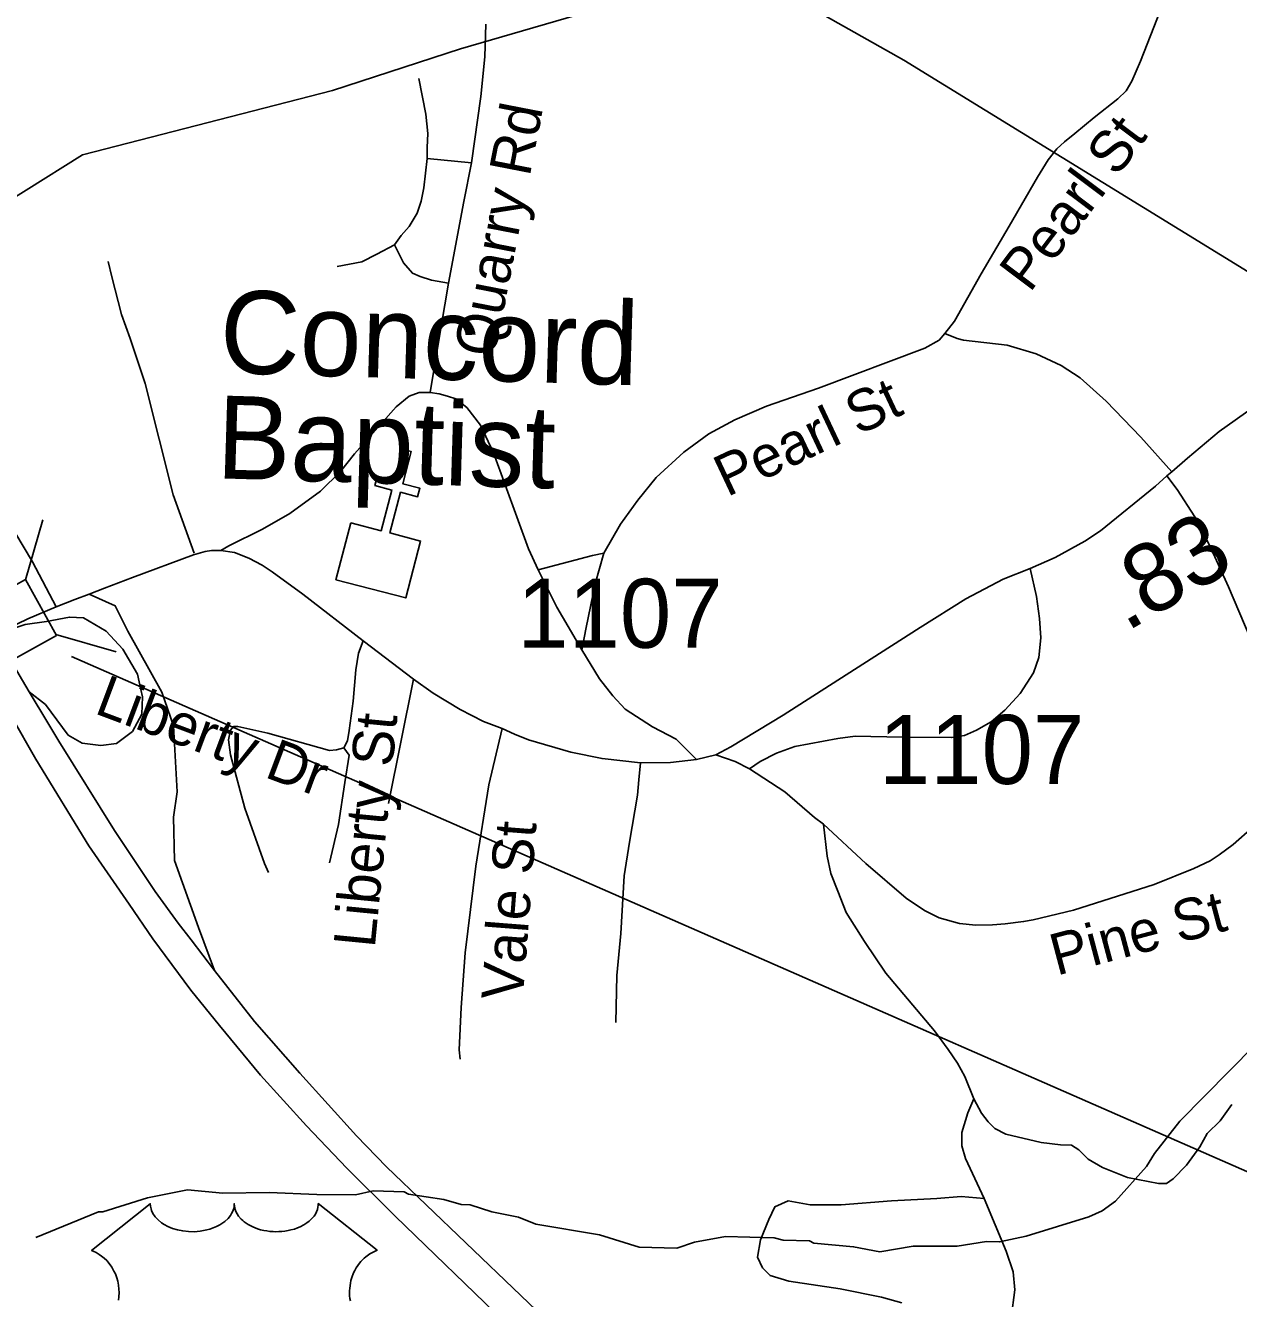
# Model space of a CAD drawing. Extents: x 1159738 to 1321356, y 736314 to 882035.
# Drawn here: x 1281308 to 1283504, y 753698 to 756002 of the extents above; entities that cross this region are included whole.
import ezdxf

# ---------------------------------------------------------------- set-up
doc = ezdxf.new("R2010")
doc.units = 0
for name, color, linetype in [('Exist Cultural Church CELL', 7, 'Continuous'), ('Exist Cultural Church Label', 7, 'Continuous'), ('Exist Hydrographic Misc Water Feature', 7, 'Continuous'), ('Exist Road Non-System Type 51', 7, 'Continuous'), ('Exist Road Non-System Type 51 Label', 7, 'Continuous'), ('Exist Road Primary Interstate Ramp 1 Lane Attributed', 7, 'Continuous'), ('Exist Road Primary US Divided Attributed', 7, 'Continuous'), ('Exist Road Primary US Shield CELL', 7, 'Continuous'), ('Exist Road Secondary Mileage Hundredths English Label', 7, 'Continuous'), ('Exist Road Secondary Structure Standard Bridge CELL', 7, 'Continuous'), ('Exist Road Secondary Structure Standard Bridge Number Label', 7, 'Continuous'), ('Exist Road Secondary Type 51 Attributed', 7, 'Continuous'), ('Exist Road Secondary Type 51 Number Label', 7, 'Continuous'), ('Exist Utilities Electrical Transmission Line', 7, 'Continuous')]:
    doc.layers.add(name, color=color, linetype=linetype)

msp = doc.modelspace()

# ---------------------------------------------------------------- linework, layer by layer
at = {"layer": 'Exist Cultural Church CELL'}
msp.add_lwpolyline([(1281897.2, 755101.7), (1281952.3, 755087.4), (1281971.6, 755161), (1281940.6, 755169.1), (1281944.7, 755184.6), (1281975.6, 755176.5), (1281990.9, 755234.6), (1282006.4, 755230.6), (1281991.1, 755172.4), (1282022.1, 755164.3), (1282018, 755148.8), (1281987.1, 755156.9), (1281967.8, 755083.3), (1282023.5, 755068.6), (1281996.5, 754965.6), (1281870.2, 754998.7)], close=True, dxfattribs=at)
at = {"layer": 'Exist Hydrographic Misc Water Feature'}
msp.add_lwpolyline([(1283532.3, 754155.9), (1283397.4, 754018.6), (1283351.8, 753960), (1283337.1, 753936.4), (1283281.3, 753874), (1283256.8, 753856.7), (1283232.5, 753845.4), (1283119.6, 753810.7), (1283071.3, 753800.1), (1283047.3, 753800.7), (1282994.6, 753792.7), (1282915, 753792.5), (1282854.7, 753782.3), (1282807, 753791.6), (1282735.1, 753797.7), (1282727.3, 753801.9), (1282679.3, 753803.3), (1282663.4, 753807.8), (1282575.5, 753810.3), (1282519.2, 753799.9), (1282486.9, 753788.8), (1282418.9, 753790.7), (1282347.4, 753812.8), (1282232, 753832.1), (1282200.3, 753845), (1282152.5, 753854.4), (1282113, 753867.5), (1282097, 753868), (1282065.2, 753876.9), (1282001.4, 753886.7), (1281993.5, 753890.9), (1281937.5, 753892.5), (1281905.3, 753885.5), (1281835.6, 753885.9), (1281749.5, 753889.9), (1281665.4, 753888.3), (1281601.6, 753894.2), (1281529.2, 753880.2), (1281448.4, 753854.6), (1281440.4, 753854.8), (1281327.1, 753808.1)], dxfattribs=at)
at = {"layer": 'Exist Road Non-System Type 51'}
msp.add_line((1282010.7, 754818.4), (1281965.2, 754593.4), dxfattribs=at)
for points in [[(1282972.4, 755444.5), (1282989.4, 755466.8), (1283038, 755552.4), (1283088.3, 755638.4), (1283140, 755727.2), (1283159.4, 755758.5), (1283175, 755778.5), (1283188.8, 755791), (1283207.6, 755806.4), (1283242.6, 755835.2), (1283285.1, 755869.2), (1283300.1, 755883.6), (1283310.8, 755901.2), (1283326.1, 755936.9), (1283362.4, 756029.5), (1283423.4, 756192.8), (1283428.8, 756213.8), (1283432.2, 756240.4), (1283432.8, 756287.9), (1283427.5, 756356.5), (1283439.4, 756408.9)], [(1280640.2, 755937), (1280709.8, 755992.4), (1280734.1, 755999.3), (1280747.9, 755988.9), (1280770.6, 755949.5), (1280815.5, 755872.8), (1280961.1, 755645.6), (1281020, 755550.2), (1281094.5, 755409.7), (1281321.2, 755031), (1281363.9, 754949.8)], [(1282115.6, 755753.4), (1282132.7, 755873.2), (1282139.6, 755944.8), (1282141.4, 756004.1)], [(1282019.9, 755906), (1282032.8, 755841.4), (1282036.3, 755806), (1282035.4, 755781), (1282035.4, 755761.2)], [(1282035.4, 755761.2), (1282029.4, 755707.7), (1282024.2, 755683.5), (1282017.3, 755662), (1282002.7, 755637.8), (1281988, 755621.4), (1281975.9, 755605)], [(1282035.4, 755761.2), (1282115.6, 755753.4)], [(1282074.1, 755535.6), (1282101.7, 755683.1), (1282115.6, 755753.4)], [(1281975.9, 755605), (1281944.1, 755587.8), (1281917.3, 755574), (1281872.5, 755565.4)], [(1281975.9, 755605), (1281992.3, 755572.3), (1282008.7, 755553.3), (1282022.4, 755547.6), (1282043.1, 755540.7), (1282074.1, 755535.6)], [(1281613.6, 755046.7), (1281575.4, 755152.5), (1281525.2, 755353.6), (1281497.5, 755435.1), (1281481.9, 755478.5), (1281464.6, 755546.9), (1281457.7, 755574.7)], [(1282074.1, 755535.6), (1282054.4, 755421.1), (1282040.6, 755337.5)], [(1282355.1, 755046.6), (1282385.3, 755099.2), (1282416.3, 755142.4), (1282449.9, 755183.8), (1282499.6, 755229.2), (1282545.3, 755262.8), (1282591.9, 755287.8), (1282649.6, 755312.8), (1282743.5, 755345.6), (1282936.2, 755417.8), (1282962, 755432.4), (1282972.4, 755444.5)], [(1282972.4, 755444.5), (1282994.7, 755435.2), (1283005.7, 755432.4), (1283084.9, 755423.4), (1283137.2, 755407.5), (1283182.9, 755386.4), (1283216.9, 755364.3), (1283264, 755321.7), (1283327, 755256.6), (1283383.1, 755194.1)], [(1282040.6, 755337.5), (1282020.8, 755337.5), (1282002.7, 755330.6), (1281979.4, 755311.6), (1281903.6, 755226.2), (1281878.7, 755194.5), (1281842.5, 755159.2), (1281786.5, 755118.6), (1281737.3, 755090.2), (1281676.2, 755060.2), (1281661.6, 755051.7)], [(1282040.6, 755337.5), (1282057.2, 755335.3), (1282071.8, 755331), (1282087.3, 755325.8), (1282107.2, 755310.3), (1282132.1, 755278.4), (1282155.4, 755228.3), (1282218.9, 755054.4), (1282236.2, 755016.4)], [(1283373.8, 755186.8), (1283392.8, 755162), (1283424.6, 755112.4), (1283451.4, 755061.2), (1283485.6, 754986), (1283545.5, 754845.4)], [(1282236.2, 755016.4), (1282334.4, 755042.3), (1282355.1, 755046.6)], [(1282315.4, 754871.5), (1282323.2, 754912.1), (1282339.6, 754991.4), (1282355.1, 755046.6)], [(1282236.2, 755016.4), (1282269.8, 754949.2), (1282315.4, 754871.5)], [(1282618.9, 754656.4), (1282637.8, 754669.7), (1282667.4, 754684.6), (1282700.6, 754697.1), (1282778.5, 754711), (1282809.9, 754715.4), (1282895.4, 754713.9), (1282984.3, 754712.8), (1283007.7, 754716.8), (1283029.6, 754726.3), (1283056, 754741.7), (1283081, 754762.3), (1283108.4, 754792.7), (1283132.6, 754830.3), (1283142.4, 754857.8), (1283145.7, 754893.2), (1283143.5, 754928.7), (1283138, 754968.4), (1283126.7, 755018.8)], [(1281884.6, 754694.3), (1281890.8, 754706.8), (1281894.4, 754725.5), (1281901.5, 754779.1), (1281906, 754835.3), (1281911.3, 754865.7), (1281919.4, 754888)], [(1282315.4, 754871.5), (1282347, 754819.3), (1282371.1, 754788.2), (1282393.5, 754764.1), (1282442.9, 754732.3), (1282485.7, 754710.2), (1282522.6, 754673.2)], [(1281884.6, 754694.3), (1281871.2, 754690.7), (1281858.7, 754689.8), (1281747.2, 754721.1), (1281692.7, 754732.7), (1281684.7, 754732.7), (1281679.4, 754726.4), (1281675.8, 754708.6), (1281679.4, 754681.8), (1281705.2, 754585.3), (1281740.9, 754485.3), (1281748.1, 754468.7)], [(1282170.9, 754729.2), (1282146.8, 754627.4), (1282123.6, 754480.1), (1282103.9, 754323.6), (1282096.8, 754224.5), (1282093.2, 754147.7), (1282095, 754130.8)], [(1281858.7, 754486.2), (1281874.8, 754555.9), (1281886.4, 754631.8), (1281894.4, 754680.9), (1281884.6, 754694.3)], [(1282557.9, 754681.7), (1282592.8, 754669.4), (1282618.9, 754656.4)], [(1282376.6, 754197.5), (1282378.4, 754282.4), (1282385.5, 754358.3), (1282391.8, 754462.7), (1282401.6, 754523.4), (1282415.8, 754608.9), (1282418.5, 754636.5), (1282421.6, 754667.2)], [(1282618.9, 754656.4), (1282682.4, 754614.7), (1282736.3, 754568.6), (1282752.7, 754556.3)], [(1282752.7, 754556.3), (1282758.9, 754498.3), (1282766.1, 754467), (1282778.6, 754434.9), (1282793.7, 754396.5), (1282826.7, 754343.8), (1282865.1, 754286.7), (1282953.3, 754182.5), (1282978.3, 754148.6), (1282995.2, 754123.6), (1283008.6, 754099.5), (1283024.7, 754059.3), (1283038.8, 754033), (1283050.4, 754017.8), (1283062.9, 754005.3), (1283082.5, 753995.5), (1283146.7, 753980.3), (1283181.5, 753975.8), (1283201.2, 753975), (1283214.5, 753966.9), (1283231.5, 753950), (1283257.4, 753934.8), (1283302.9, 753916.9), (1283359.1, 753906.2), (1283373.3, 753906.2), (1283385.6, 753914.2), (1283409.7, 753939.2), (1283433.8, 753972.3), (1283447.1, 753996.4), (1283470.3, 754019.6), (1283491.7, 754049.1)], [(1283529.7, 754551), (1283494.2, 754519.6), (1283468.7, 754500.8), (1283452.6, 754489.6), (1283422.9, 754476), (1283351, 754447.1), (1283205, 754400.5), (1283132.2, 754383.2), (1283114.8, 754379.9), (1283081.4, 754375.8), (1283058.3, 754374.1), (1283028.1, 754373.7), (1282998.5, 754376.2), (1282962.2, 754386.5), (1282935.4, 754400.2), (1282902.3, 754422.1), (1282828.9, 754485.3), (1282752.7, 754556.3)], [(1283024.7, 754059.3), (1283013.8, 754034.1), (1283003.1, 753998.4), (1283003.1, 753974.3), (1283009.3, 753951.1), (1283043.2, 753878.8)], [(1282894.3, 753689.7), (1282857.7, 753700.4), (1282782.7, 753715.5), (1282689.9, 753728.9), (1282656.3, 753739.6), (1282642, 753753), (1282633.1, 753772.6), (1282638.4, 753803.9), (1282653.6, 753840.5), (1282664.3, 753863.7), (1282688.4, 753874.4), (1282728.5, 753867.3), (1282784.7, 753867.3), (1282875.7, 753874.4), (1282957.8, 753878.9), (1283001.5, 753882.5), (1283043.2, 753878.8)], [(1283043.2, 753878.8), (1283083.4, 753783.3), (1283095.9, 753745.8), (1283098.6, 753713.6), (1283092.3, 753662.9)]]:
    msp.add_lwpolyline(points, dxfattribs=at)
at = {"layer": 'Exist Road Primary Interstate Ramp 1 Lane Attributed'}
for points in [[(1281650.6, 754291.4), (1281621.6, 754369.4), (1281577.8, 754490.3), (1281576, 754569.2), (1281583, 754614.8), (1281576, 754734), (1281555, 754795.3), (1281493.6, 754905.7), (1281470.8, 754951.3), (1281423.3, 754972.5)], [(1281253.5, 754899.5), (1281307.6, 754917.6), (1281346.6, 754923.1), (1281387.7, 754930.9), (1281413.2, 754929.8), (1281454.3, 754905.3), (1281484.4, 754873.2), (1281511, 754827.6), (1281517, 754799.9)], [(1281517, 754799.9), (1281520, 754786.5), (1281518.8, 754755.3), (1281502.1, 754724.2), (1281473.3, 754702), (1281444.4, 754698.7), (1281411.1, 754703.1), (1281385.4, 754717.5), (1281344.3, 754773.1), (1281315, 754795.8)]]:
    msp.add_lwpolyline(points, dxfattribs=at)
at = {"layer": 'Exist Road Primary US Divided Attributed'}
for points in [[(1281315, 754795.8), (1281308.9, 754806), (1281253.5, 754899.5)], [(1281205.3, 754875), (1281282.7, 754750.9), (1281327.3, 754673.8), (1281422.8, 754516.8), (1281495.9, 754411.3), (1281539, 754348.9), (1281607.8, 754256.1), (1281659.7, 754192.1), (1281733.9, 754102), (1281817.1, 754010.1), (1281889.7, 753933.7), (1281977.6, 753846.5), (1282175.6, 753654.8), (1282321.8, 753516.3), (1282602, 753249.9), (1282794.5, 753067.1), (1282993.2, 752875.7), (1283115.9, 752762.2), (1283169.4, 752712.1), (1283311, 752579.4), (1283449.2, 752449), (1283551.7, 752350.5), (1283622.4, 752282.2), (1284370.9, 751572.6)], [(1281650.6, 754291.4), (1281608.1, 754346.9), (1281584.4, 754376.9), (1281543.3, 754434.6), (1281469.6, 754544.5), (1281368.7, 754706.3), (1281348.8, 754739.4), (1281315, 754795.8)], [(1284406.3, 751613.3), (1283745.3, 752241.8), (1283636.2, 752347), (1283590.4, 752388.5), (1283450.2, 752521.5), (1283263.2, 752698.3), (1283203.3, 752756.5), (1282971, 752973.8), (1282755.9, 753180.7), (1282403.6, 753512.5), (1282105.3, 753798.8), (1281961.9, 753936.1), (1281907.4, 753991.9), (1281804.9, 754105.5), (1281722.9, 754199.3), (1281650.6, 754291.4)]]:
    msp.add_lwpolyline(points, dxfattribs=at)
at = {"layer": 'Exist Road Primary US Shield CELL'}
msp.add_lwpolyline([(1281476.5, 753694.8), (1281477.3, 753700.9), (1281477.6, 753708.5), (1281477.5, 753714.8), (1281476.6, 753722.2), (1281475.3, 753729.2), (1281473.6, 753735.4), (1281471, 753742.4), (1281468.5, 753747.5), (1281464.5, 753754.5), (1281459.9, 753761), (1281455.3, 753766.3), (1281450.6, 753771), (1281446, 753774.5), (1281441.7, 753777.6), (1281436.3, 753780.8), (1281431.1, 753783.4), (1281427.9, 753784.7), (1281534.1, 753869.4), (1281534.4, 753865), (1281535.5, 753859.8), (1281536.3, 753857.1), (1281538.7, 753851.9), (1281542.8, 753845.8), (1281548.4, 753839.9), (1281554.7, 753834.6), (1281559, 753831.9), (1281566.2, 753828), (1281574.5, 753824.5), (1281583.6, 753821.9), (1281593, 753820), (1281603.2, 753818.9), (1281613.3, 753818.7), (1281624.2, 753819.5), (1281636.3, 753821.8), (1281641.9, 753823.3), (1281648.1, 753825.4), (1281653.9, 753827.8), (1281660.2, 753831.2), (1281665.3, 753834.5), (1281669.3, 753837.3), (1281674.9, 753842.7), (1281679.4, 753848.3), (1281681.3, 753851.5), (1281682.9, 753854.5), (1281685.1, 753860.9), (1281685.8, 753863.7), (1281686.2, 753869.6), (1281686.6, 753864.7), (1281687.1, 753861.6), (1281687.9, 753858.6), (1281689.2, 753855.4), (1281691.4, 753850.8), (1281693.9, 753847.1), (1281698.7, 753841.5), (1281701.6, 753838.7), (1281704.3, 753836.5), (1281711.5, 753831.6), (1281720, 753827.3), (1281724.1, 753825.5), (1281728.4, 753824), (1281733.8, 753822.3), (1281739.4, 753821), (1281744.9, 753820.1), (1281750.5, 753819.3), (1281756.3, 753818.8), (1281761, 753818.7), (1281766.8, 753818.8), (1281772.1, 753819.1), (1281777.6, 753819.7), (1281783.6, 753820.7), (1281788.5, 753821.8), (1281794.9, 753823.5), (1281800.6, 753825.5), (1281805.7, 753827.7), (1281812.3, 753831.2), (1281817.6, 753834.5), (1281821.5, 753837.7), (1281826.2, 753841.9), (1281830.6, 753847), (1281833.2, 753850.7), (1281835, 753854.5), (1281836.7, 753858.6), (1281837.7, 753862.8), (1281838.2, 753866.5), (1281838.3, 753869.7), (1281944.6, 753785), (1281942.1, 753784.1), (1281936.3, 753781.3), (1281931.7, 753778.6), (1281924.4, 753773.4), (1281921.3, 753770.6), (1281918.1, 753767.6), (1281915.2, 753764.5), (1281912.7, 753761.5), (1281909.6, 753757.3), (1281906.9, 753753), (1281904.2, 753748.3), (1281902.2, 753744.2), (1281898.9, 753735.7), (1281897.4, 753730.3), (1281896.4, 753725.7), (1281895.1, 753716.2), (1281894.8, 753711.7), (1281894.8, 753707.2), (1281895, 753702.5), (1281895.5, 753698), (1281896.3, 753693.3)], dxfattribs=at)
at = {"layer": 'Exist Road Secondary Structure Standard Bridge CELL'}
for p, q in [((1281308.6, 754998.5), (1281339.8, 755107.3)), ((1281363.5, 754899.5), (1281472.3, 754868.3))]:
    msp.add_line(p, q, dxfattribs=at)
msp.add_lwpolyline([(1281091.6, 754878.7), (1281308.4, 754998.9), (1281364.5, 754897.7), (1281147.8, 754777.4)], close=True, dxfattribs=at)
at = {"layer": 'Exist Road Secondary Structure Standard Bridge Number Label'}
msp.add_line((1281391.7, 754859.8), (1283528.6, 753923.7), dxfattribs=at)
at = {"layer": 'Exist Road Secondary Type 51 Attributed'}
for points in [[(1281423.3, 754972.5), (1281451.5, 754983.3), (1281501.9, 755002.7), (1281612.1, 755043.9), (1281633.3, 755049.8), (1281644.9, 755051.7), (1281661.6, 755051.7), (1281686.5, 755047.6), (1281712.5, 755037.5), (1281736.7, 755024.9), (1281754.8, 755013.1), (1281810.2, 754972.5), (1281919.4, 754888), (1282010.7, 754818.4), (1282046.4, 754793.5), (1282095, 754763.8), (1282137, 754742.3), (1282170.9, 754729.2), (1282193.1, 754718.9), (1282218.8, 754708.8), (1282295, 754686.5), (1282351.9, 754675), (1282421.6, 754667.2), (1282475.4, 754667.6), (1282522.6, 754673.2), (1282557.9, 754681.7), (1282585, 754696.2), (1282679.5, 754753.5), (1282824, 754845.6), (1282927.6, 754912.1), (1283009.9, 754964), (1283077.7, 754999.5), (1283126.7, 755018.8), (1283171.7, 755039), (1283225.3, 755068.5), (1283254.1, 755087.3), (1283353.5, 755168), (1283373.8, 755186.8), (1283383.1, 755194.1), (1283411.5, 755218.4), (1283468.7, 755266.8), (1283530.5, 755310.7)], [(1281253.5, 754899.5), (1281312.8, 754927.9), (1281363.9, 754949.8), (1281397.7, 754962.7), (1281423.3, 754972.5)]]:
    msp.add_lwpolyline(points, dxfattribs=at)
at = {"layer": 'Exist Utilities Electrical Transmission Line'}
for points in [[(1280745.9, 755440), (1281049.7, 755527.6), (1281206.7, 755639.8), (1281411.7, 755767.4), (1281863.7, 755883.9), (1282095.8, 755959.7), (1282380.5, 756041.9), (1282514.6, 756042.8), (1282689, 756057.4)], [(1284421, 754681.5), (1284272.9, 754942.1), (1284123.7, 755158.6), (1283958.9, 755398.1), (1283875.3, 755458.8), (1283703.2, 755456.6), (1283544.4, 755541.3), (1282897.7, 755938.8), (1282689, 756057.4)]]:
    msp.add_lwpolyline(points, dxfattribs=at)

# ---------------------------------------------------------------- texts
at = {"layer": 'Exist Cultural Church Label'}
for s, p in [('Concord', (1281658.3, 755373.3)), ('Baptist', (1281652.5, 755182.3))]:
    msp.add_text(s, height=150, rotation=358.2634, dxfattribs=at).set_placement(p)
at = {"layer": 'Exist Road Non-System Type 51 Label'}
for s, rotation, p in [('Quarry Rd', 78.9719, (1282156.7, 755398.3)), ('Pearl St', 53.0553, (1283126, 755516.5)), ('Pearl St', 25.2175, (1282578, 755147.7)), ('Liberty Dr', 339.4554, (1281430.9, 754757.6)), ('Liberty St', 84.4283, (1281940.4, 754331)), ('Vale St', 85.5334, (1282208, 754235.7)), ('Pine St', 14.8879, (1283174.5, 754281.8))]:
    msp.add_text(s, height=75, rotation=rotation, dxfattribs=at).set_placement(p)
at = {"layer": 'Exist Road Secondary Mileage Hundredths English Label'}
msp.add_text('.83', height=125, rotation=30.2899, dxfattribs=at).set_placement((1283300.4, 754903.4))
at = {"layer": 'Exist Road Secondary Type 51 Number Label'}
for p in [(1282198.1, 754875.4), (1282852.8, 754629), (1282852.8, 754629), (1282852.8, 754629), (1282852.8, 754629), (1282852.8, 754629), (1282852.8, 754629)]:
    msp.add_text('1107', height=125, dxfattribs=at).set_placement(p)

doc.saveas('drawing.dxf')
